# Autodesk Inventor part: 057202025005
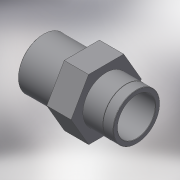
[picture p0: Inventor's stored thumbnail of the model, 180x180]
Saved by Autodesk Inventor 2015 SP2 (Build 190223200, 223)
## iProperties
Created: 2017-10
Part Number: 057202025005
Material: Generic
Description: PLASSON REDUCER THR-CEM REIN 25-(20)-1/2"
Document SubType Name: Modeling
Designer: KIM
Density: 1 g/cm^3
Appearance: Default
Author: KIM
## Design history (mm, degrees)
derived "057202.ipt"
feature "Solid1::057202.ipt"
tag "TaggingFeature1"
body "Solid1"
other parameters: "d0" = 46, "d3" = 18.631, "d4" = 18, "d6" = 17, "d7" = 25, "d8" = 23, "d13" = 0, "d14" = 0.2, "d16" = 12, "d17" = 19, "d18" = 20.4, "d19" = 0.1, "d20" = 5.1, "d21" = 23, "G_" = 18.631, "B_" = 12, "L_" = 19, "lt_" = 17, "H_" = 46, "D_" = 25
